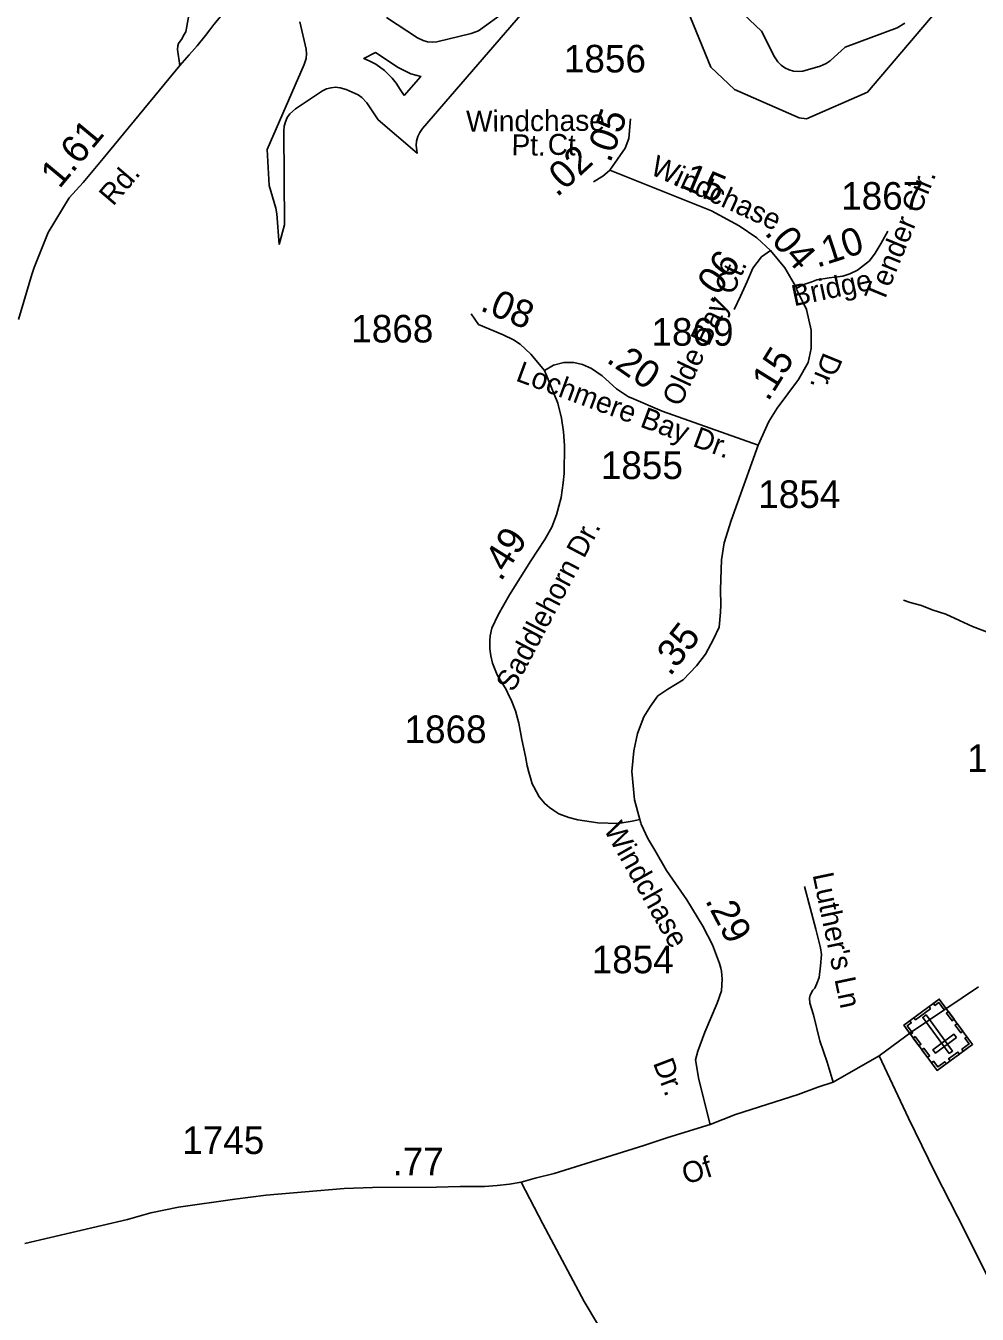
# Model space of a CAD drawing. Extents: x 2220236 to 2384410, y 720751 to 894131.
# Drawn here: x 2321364 to 2325675, y 772786 to 778623 of the extents above; entities that cross this region are included whole.
import ezdxf

# ---------------------------------------------------------------- set-up
doc = ezdxf.new("R2010")
doc.units = 0
doc.layers.add('Default', color=7, linetype='Continuous')

msp = doc.modelspace()

# ---------------------------------------------------------------- linework, layer by layer
at = {"layer": 'Default'}
for points in [[(2322414.6, 778950.2), (2322399.3, 778914.8), (2322377.2, 778865.6), (2322359.1, 778829.3), (2322346.2, 778805.3), (2322324.2, 778765.8), (2322294.4, 778721.7), (2322271.1, 778695.2), (2322247.8, 778665.4), (2322216.7, 778627.8), (2322197.3, 778604.5), (2322179.1, 778577.9), (2322141.2, 778532.3), (2322104, 778491.7), (2322062.6, 778441.9), (2321714.2, 778020.7), (2321623.6, 777911.9), (2321561.2, 777843.4), (2321465.6, 777686.4), (2321402.2, 777527.1), (2321391.1, 777495.8), (2321331.6, 777291.9)], [(2325619.5, 778841.8), (2325177.4, 778322.3), (2324900.8, 778201.6), (2324868, 778205.5), (2324575.8, 778334.3), (2324467.3, 778434.6), (2324349.2, 778726)], [(2324477, 778807.7), (2324698.2, 778598.1), (2324756.7, 778481.9), (2324772, 778458.7), (2324786.8, 778443.9), (2324804, 778431.9), (2324822.9, 778423.1), (2324843.2, 778417.6), (2324863.9, 778415.8), (2324884.8, 778417.6), (2324964, 778439.6), (2324991, 778451), (2325008.3, 778463.1), (2325077, 778526.4), (2325312, 778614), (2325347.2, 778634.5)], [(2323710.7, 778794), (2323162, 778157.8), (2323149.1, 778139.6), (2323140.2, 778120.6), (2323134.7, 778100.4), (2323133.1, 778079.6), (2323136.8, 778045.3), (2322960.4, 778196.9), (2322909.8, 778272.8), (2322887.2, 778297.9), (2322870, 778309.9), (2322815.2, 778334.3), (2322788.8, 778342.1), (2322768.1, 778344), (2322747.2, 778342.1), (2322727.1, 778336.7), (2322708, 778327.9), (2322586.2, 778246.8), (2322561, 778224.1), (2322548.9, 778207), (2322540.3, 778188.1), (2322534.7, 778167.8), (2322532.9, 778147), (2322536.8, 777720.2), (2322511.8, 777631.5)], [(2322062.6, 778441.9), (2322051.7, 778514.5), (2322053.6, 778532.4), (2322055.4, 778542.4), (2322073.3, 778564.6), (2322079.1, 778578.6), (2322088.9, 778594.8), (2322107.7, 778697)], [(2322999.2, 778659.8), (2323139.2, 778568), (2323164, 778555.6), (2323184.3, 778550.2), (2323205, 778548.4), (2323225.8, 778550.2), (2323382.8, 778587.3), (2323415, 778600.1), (2323540.5, 778690.4)], [(2322511.8, 777631.5), (2322501.7, 777770.5), (2322497, 777796.3), (2322466.2, 777899), (2322458.2, 778062.7), (2322626, 778447.9), (2322634.2, 778475.1), (2322636, 778495.9), (2322634.2, 778516.7), (2322605.9, 778640)], [(2323079.1, 778307), (2323060.9, 778334.3), (2323042.4, 778361.9), (2323024.4, 778386), (2322989.9, 778420.5), (2322950, 778448.5), (2322920.2, 778463.3), (2322895.4, 778474), (2322948.9, 778501.4), (2323051.5, 778434.1), (2323109.3, 778405.3), (2323153.6, 778393.4), (2323079.1, 778307)], [(2324010.9, 777968.5), (2324080.3, 778067.6), (2324096.8, 778112.2), (2324103.4, 778201.5)], [(2323936.6, 777915.6), (2323977.9, 777942), (2323997.7, 777957.7), (2324010.9, 777968.5)], [(2324737.8, 777604.8), (2324676.7, 777661.4), (2324596, 777716.9), (2324470.4, 777784.6), (2324010.9, 777968.5)], [(2324853.9, 777432), (2324889.4, 777450.4), (2324925.8, 777462), (2324947.9, 777472.2), (2325004.2, 777481.1), (2325066.2, 777488.5), (2325098, 777499.1), (2325132.3, 777515.4), (2325186.7, 777557.8), (2325213.1, 777592.5), (2325239.5, 777637.2), (2325269.3, 777691.7)], [(2324737.8, 777604.8), (2324697.9, 777575.2), (2324678.1, 777550.4), (2324658.2, 777524), (2324632.3, 777463.6), (2324602.5, 777397.5), (2324573.8, 777337.6)], [(2324856.5, 777435.3), (2324803.2, 777526.8), (2324737.8, 777604.8)], [(2324682.9, 776723), (2324731.4, 776830.2), (2324768.9, 776890.6), (2324864.7, 777020), (2324909.3, 777097.6), (2324922.5, 777160.4), (2324922.5, 777243), (2324901, 777337.2), (2324859.7, 777423.2), (2324853.9, 777432)], [(2323714.5, 777061.2), (2323652.3, 777135.2), (2323604.5, 777180.8), (2323573.4, 777199.5), (2323526.6, 777222.6), (2323415.7, 777269.9), (2323381.8, 777317.4)], [(2324146.6, 775027.2), (2324112, 775020), (2324047.6, 775008.5), (2323956.7, 775011.8), (2323865.9, 775025), (2323824.6, 775036.5), (2323780, 775053.1), (2323756.9, 775067.9), (2323737.1, 775081.2), (2323715.6, 775099.3), (2323690.9, 775129.1), (2323665.5, 775174.6), (2323658.9, 775187.8), (2323650.5, 775215.4), (2323643.7, 775241.9), (2323636.1, 775270.3), (2323627.6, 775313), (2323611.7, 775389), (2323598.1, 775463.4), (2323583.3, 775519.5), (2323563.8, 775569.1), (2323554.9, 775586), (2323540.3, 775615.2), (2323513.4, 775660), (2323499.3, 775682.8), (2323490.9, 775704.8), (2323478.6, 775735.1), (2323471.2, 775768.7), (2323466.3, 775800.1), (2323466.3, 775836.5), (2323467.9, 775859.6), (2323476.2, 775894.3), (2323504.3, 775953.8), (2323555.4, 776044.7), (2323652.4, 776198.9), (2323716.1, 776295.3), (2323747, 776351.2), (2323768.2, 776407.2), (2323789.5, 776486.2), (2323799.1, 776551.8), (2323803, 776594.3), (2323804.9, 776721.6), (2323801.1, 776783.3), (2323791.4, 776845), (2323774, 776912.5), (2323714.5, 777061.2)], [(2324682.9, 776723), (2324246.9, 776876.7), (2324106.5, 776936.6), (2324095.5, 776942.2), (2324041.3, 776977.8), (2323976, 777037.4), (2323926.7, 777070), (2323887.1, 777088), (2323847.3, 777097), (2323832.6, 777096.9), (2323802.3, 777097.8), (2323755, 777085.5), (2323714.5, 777061.2)], [(2324146.6, 775027.2), (2324122.6, 775116.8), (2324110.5, 775245.1), (2324118.6, 775337.3), (2324136.4, 775416.3), (2324164.5, 775492.3), (2324194.2, 775540.2), (2324227.2, 775586.5), (2324273.5, 775617), (2324342.8, 775660), (2324402.3, 775722.8), (2324443.6, 775775.7), (2324479.9, 775843.4), (2324505, 775897.7), (2324511.7, 775966.5), (2324513.7, 775998.1), (2324512.5, 776068.5), (2324515.9, 776202.7), (2324528.4, 776279.6), (2324560.6, 776381.6), (2324682.9, 776723)], [(2326214.3, 775674.5), (2325848.7, 775827.6), (2325654, 775901.3), (2325594.6, 775928.8), (2325532, 775957.5), (2325471.5, 775977.3), (2325422, 775997.1), (2325371.4, 776010.3), (2325340.6, 776021.3)], [(2324465.5, 773644.6), (2324413.9, 773849.3), (2324399, 773939), (2324408.9, 773977), (2324440.3, 774062.9), (2324496.4, 774194.3), (2324516.2, 774250.5), (2324519.5, 774304.2), (2324516.2, 774339.7), (2324512.9, 774352.9), (2324507.5, 774375), (2324475.4, 774459.2), (2324431.3, 774543.4), (2324359.1, 774663.7), (2324266.9, 774796), (2324214.8, 774888.2), (2324182.7, 774940.4), (2324152.9, 775006.1), (2324150.6, 775012.5), (2324146.6, 775027.2)], [(2324893.1, 774722.8), (2324943.1, 774529.6), (2324965.2, 774445.5), (2324970.1, 774415.2), (2324965.2, 774364.4), (2324959.2, 774311.2), (2324948.3, 774283.4), (2324939.9, 774263.5), (2324930.1, 774253.5), (2324918.3, 774231.3), (2324914.5, 774217.3), (2324916.8, 774195.4), (2324933.3, 774141.7), (2324962.4, 774024), (2324995.6, 773928.3), (2325022.6, 773836.6)], [(2325681.5, 774269.6), (2325379.9, 774066.4), (2325231.2, 773957), (2325022.6, 773836.6), (2324953.2, 773813.8), (2324864.3, 773781.1), (2324579.7, 773690.4), (2324465.5, 773644.6)], [(2325231.2, 773957), (2325364.1, 773674.5), (2325484.9, 773425.9), (2325619.5, 773163.4), (2325727.6, 772944.7), (2325819.5, 772775.8), (2325978.1, 772531.6), (2326055.3, 772420.5), (2326097.8, 772363), (2326118, 772345.2), (2326146.1, 772331.6), (2326198.3, 772312.1)], [(2324465.5, 773644.6), (2324273.5, 773586.8), (2324164, 773549.6), (2323757.7, 773423.2), (2323671.9, 773402.3), (2323608, 773383.7), (2323556.2, 773375.1), (2323500.4, 773368.5), (2323442.4, 773363.9), (2323332.5, 773364.6), (2323224.6, 773361.6), (2322934.8, 773360.4), (2322806.8, 773355), (2322453.3, 773325.2), (2322311.5, 773307.8), (2322056.2, 773271), (2321930.3, 773245.7), (2321824.8, 773214.5), (2321360.1, 773105.6)], [(2323608, 773383.7), (2323706.1, 773194.8), (2323893.7, 772842.9), (2324009.9, 772648.4)]]:
    msp.add_lwpolyline(points, dxfattribs=at)
for points in [[(2325653.7, 774008.1), (2325493.4, 773890.2), (2325342.5, 774095.3), (2325502.8, 774213.3)], [(2325476.2, 774193.6), (2325483, 774184.4), (2325500.8, 774197.4), (2325524.7, 774164.9), (2325533.7, 774171.5), (2325502.9, 774213.3)], [(2325463.4, 774170), (2325395, 774119.7), (2325388.3, 774128.9), (2325456.6, 774179.2)], [(2325548.5, 773967.2), (2325563.6, 773978.2), (2325443.4, 774141.6), (2325428.4, 774130.5)], [(2325544.3, 774156.9), (2325570, 774122.1), (2325560.8, 774115.3), (2325535.2, 774150.2)], [(2325369.2, 774114.9), (2325376, 774105.7), (2325358.3, 774092.6), (2325382.2, 774060.1), (2325373.2, 774053.5), (2325342.5, 774095.3)], [(2325584.1, 774102.8), (2325609.8, 774067.9), (2325600.6, 774061.2), (2325575, 774096)], [(2325394.5, 774043.8), (2325420.1, 774008.9), (2325411, 774002.2), (2325385.3, 774037.1)], [(2325580.5, 774038.8), (2325569.5, 774053.8), (2325474.6, 773984.1), (2325485.7, 773969)], [(2325628.1, 774043), (2325618.9, 774036.3), (2325638, 774010.4), (2325605.3, 773986.4), (2325611.9, 773977.4), (2325653.7, 774008.1)], [(2325433.5, 773990.7), (2325459.2, 773955.8), (2325450, 773949.1), (2325424.3, 773984)], [(2325594.1, 773964.3), (2325552.3, 773933.6), (2325545.5, 773942.8), (2325587.3, 773973.5)], [(2325467.6, 773925.1), (2325476.7, 773931.8), (2325495.8, 773905.9), (2325528.5, 773929.9), (2325535.1, 773920.9), (2325493.3, 773890.2)]]:
    msp.add_lwpolyline(points, close=True, dxfattribs=at)

# ---------------------------------------------------------------- texts
for s, p in [('1856', (2323802.1, 778411.1)), ('1867', (2325058.4, 777789.5)), ('1868', (2322838.8, 777187.9)), ('1869', (2324198.9, 777173.4)), ('1855', (2323969.5, 776569.2)), ('1854', (2324682.9, 776438.4)), ('1868', (2323080.1, 775373.3)), ('1745', (2325629, 775242)), ('1854', (2323928.2, 774330.5)), ('1745', (2322072.6, 773511.5))]:
    msp.add_text(s, height=125, dxfattribs=at).set_placement(p)
for s, height, rotation, p in [('Windchase', 95, 0.43903, (2323359.5, 778142.6)), ('.05', 125, 70.1915, (2324012.4, 777998.2)), ('1.61', 125, 50.21231, (2321516.4, 777880.9)), ('Pt.', 95, 359.09503, (2323564.4, 778036.2)), ('Ct.', 95, 358.20181, (2323727.6, 778039.2)), ('.02', 125, 42.66263, (2323770.9, 777843.3)), ('Windchase', 95, 335.51648, (2324187.3, 777952.9)), ('.15', 125, 337.27964, (2324287.1, 777908.3)), ('Rd.', 95, 49.48367, (2321759.7, 777802.2)), ('Tender Cir.', 95, 67.68884, (2325249.3, 777362.7)), ('.04', 125, 310.86963, (2324707.8, 777682.2)), ('.10', 125, 18.14809, (2324949.5, 777525.9)), ('.06', 125, 54.93731, (2324473.1, 777356.9)), ('Olde Bay Ct.', 95, 64.91828, (2324329.2, 776892.5)), ('Bridge ', 95, 12.00289, (2324845, 777351.6)), ('.08', 125, 337.21497, (2323417.8, 777334.9)), ('.20', 125, 325.12021, (2323989.7, 777102)), ('.15', 125, 58.13606, (2324727.5, 776916.9)), ('Dr.', 95, 247.68884, (2324979.5, 777148.1)), ('Lochmere Bay Dr.', 95, 339.7091, (2323579.5, 777016.1)), ('Saddlehorn Dr.', 95, 62.16206, (2323573.1, 775600.1)), ('.49', 125, 57.83482, (2323517.3, 776101.5)), ('.35', 125, 52.01959, (2324283.3, 775672)), ('Windchase', 95, 299.47608, (2323980.2, 774983)), ("Luther's Ln", 95, 281.85176, (2324928.4, 774776.9)), ('.29', 125, 297.64589, (2324440.4, 774660.7)), ('Dr.', 95, 290.85462, (2324204.7, 773924.3)), ('.77', 125, 0.2374, (2323026, 773415)), ('Of', 95, 17.4666, (2324354.6, 773372.6))]:
    msp.add_text(s, height=height, rotation=rotation, dxfattribs=at).set_placement(p)

doc.saveas('drawing.dxf')
